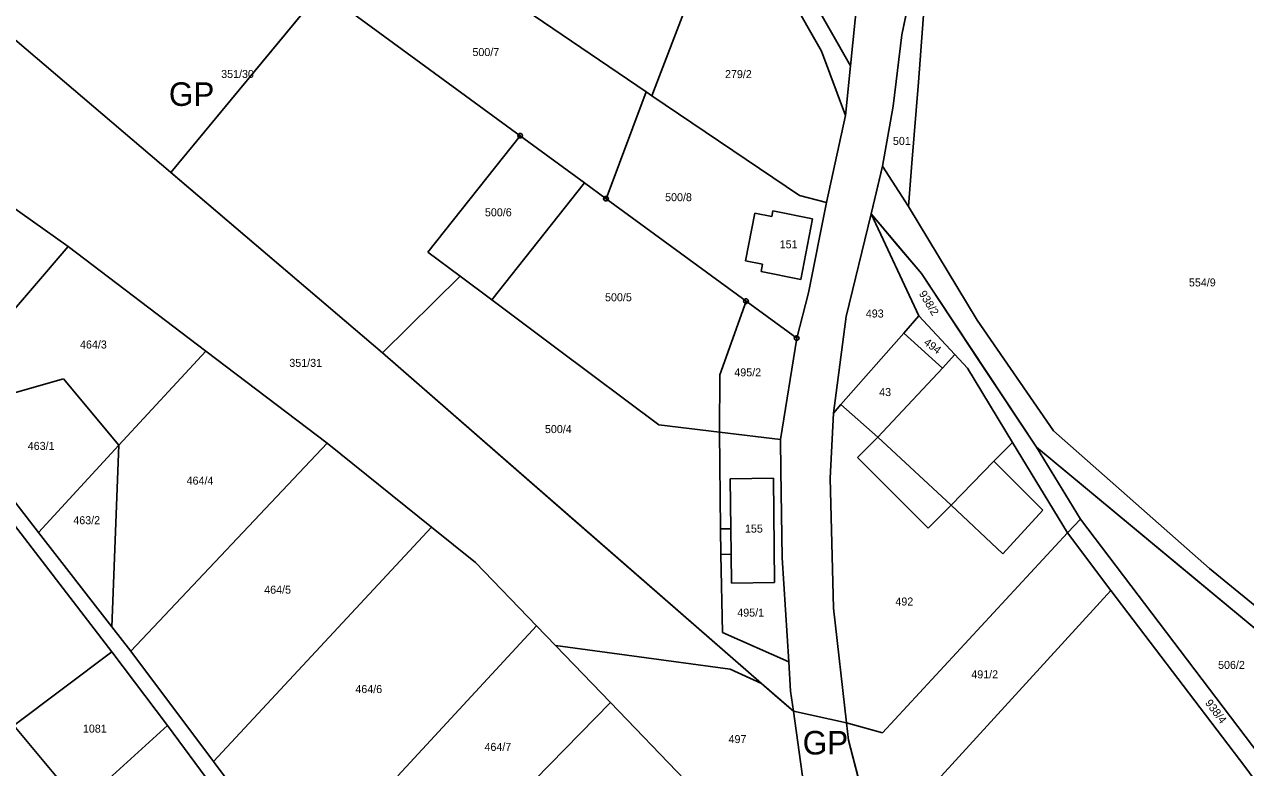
# Model space of a CAD drawing. Extents: x -593358 to -590116, y -1072518 to -1068420.
# Drawn here: x -591991 to -591731.6, y -1071381.6 to -1071223.8 of the extents above; entities that cross this region are included whole.
import ezdxf

# ---------------------------------------------------------------- set-up
doc = ezdxf.new("R2010")
doc.units = 0
for name, color, linetype in [('GP', 7, 'Continuous'), ('Parcela KN', 7, 'Continuous'), ('Parcela ZE', 7, 'Continuous'), ('Parcelní číslo', 7, 'Continuous'), ('Parcelní číslo_stavební', 7, 'Continuous'), ('stavby - vnitřní kresba', 7, 'Continuous'), ('Vnitřní obvod', 7, 'Continuous'), ('Vrstva 24', 7, 'Continuous')]:
    doc.layers.add(name, color=color, linetype=linetype)

msp = doc.modelspace()

# ---------------------------------------------------------------- linework, layer by layer
at = {"layer": 'GP'}
for p, q in [((-591927.89, -1071216.58), (-591959.895, -1071255.245)), ((-591827.65, -1071369.65), (-591816.36, -1071372.12))]:
    msp.add_line(p, q, dxfattribs=at)
at = {"layer": 'Parcela KN'}
for p, q in [((-591811.35, -1071191.44), (-591815.51, -1071232.63)), ((-591804.64, -1071226.05), (-591797.92, -1071193.88)), ((-591801.11, -1071236.11), (-591797.92, -1071193.88)), ((-591915.46, -1071199.67), (-591858.93, -1071238.14)), ((-591843.51, -1071202.01), (-591857.72, -1071238.98)), ((-591829.31, -1071216.03), (-591821.68, -1071229.47)), ((-591825.69, -1071214.74), (-591815.51, -1071232.63)), ((-591885.68, -1071247.47), (-591927.89, -1071216.58)), ((-591806.43, -1071241.17), (-591804.64, -1071226.05)), ((-591821.68, -1071229.47), (-591816.56, -1071243.14)), ((-591815.51, -1071232.63), (-591816.56, -1071243.14)), ((-591801.11, -1071236.11), (-591802.48, -1071253.26)), ((-591858.93, -1071238.14), (-591867.44, -1071260.82)), ((-591858.93, -1071238.14), (-591858.21, -1071238.63)), ((-591857.72, -1071238.98), (-591858.21, -1071238.63)), ((-591857.72, -1071238.98), (-591826.33, -1071260.13)), ((-591808.76, -1071253.92), (-591806.43, -1071241.17)), ((-591816.56, -1071243.14), (-591820.63, -1071261.64)), ((-591885.68, -1071247.47), (-591905.3, -1071272.14)), ((-591885.68, -1071247.47), (-591872, -1071257.48)), ((-591811.14, -1071264.07), (-591808.76, -1071253.92)), ((-591808.76, -1071253.92), (-591803.22, -1071262.48)), ((-591802.48, -1071253.26), (-591803.22, -1071262.48)), ((-591872, -1071257.48), (-591891.72, -1071282.28)), ((-591872, -1071257.48), (-591867.44, -1071260.82)), ((-591826.33, -1071260.13), (-591820.63, -1071261.64)), ((-591867.44, -1071260.82), (-591837.71, -1071282.58)), ((-591820.63, -1071261.64), (-591824.43, -1071280.83)), ((-591803.22, -1071262.48), (-591788.63, -1071286.6)), ((-591835.86, -1071263.9), (-591837.84, -1071274.01)), ((-591832.23, -1071264.61), (-591835.86, -1071263.9)), ((-591832, -1071263.43), (-591832.23, -1071264.61)), ((-591823.6, -1071265.11), (-591832, -1071263.43)), ((-591826.07, -1071277.95), (-591823.6, -1071265.11)), ((-591811.14, -1071264.07), (-591816.47, -1071285.84)), ((-591800.47, -1071276.72), (-591811.14, -1071264.07)), ((-591811.14, -1071264.07), (-591801, -1071285.7)), ((-591905.3, -1071272.14), (-591898.39, -1071277.29)), ((-591837.84, -1071274.01), (-591834.2, -1071274.72)), ((-591834.2, -1071274.72), (-591834.51, -1071276.29)), ((-591898.39, -1071277.29), (-591914.91, -1071293.58)), ((-591898.39, -1071277.29), (-591891.72, -1071282.28)), ((-591834.51, -1071276.29), (-591826.07, -1071277.95)), ((-591776, -1071313.59), (-591800.47, -1071276.72)), ((-591824.43, -1071280.83), (-591826.95, -1071290.45)), ((-591891.72, -1071282.28), (-591877.8, -1071292.68)), ((-591843.28, -1071298.24), (-591837.71, -1071282.58)), ((-591837.71, -1071282.58), (-591826.95, -1071290.45)), ((-591816.47, -1071285.84), (-591819.12, -1071306.37)), ((-591804.22, -1071289.36), (-591801, -1071285.7)), ((-591801, -1071285.7), (-591793.35, -1071293.87)), ((-591788.63, -1071286.6), (-591772.44, -1071310.09)), ((-591830.36, -1071311.96), (-591826.95, -1071290.45)), ((-591804.22, -1071289.36), (-591817.6, -1071304.55)), ((-591795.95, -1071296.77), (-591804.22, -1071289.36)), ((-591914.91, -1071293.58), (-591834.43, -1071363.74)), ((-591877.8, -1071292.68), (-591856.2, -1071308.84)), ((-591793.35, -1071293.87), (-591795.95, -1071296.77)), ((-591793.35, -1071293.87), (-591790.71, -1071296.8)), ((-591790.71, -1071296.8), (-591781.14, -1071312.56)), ((-591843.34, -1071310.39), (-591843.28, -1071298.24)), ((-591817.6, -1071304.55), (-591819.12, -1071306.37)), ((-591817.6, -1071304.55), (-591809.71, -1071311.44)), ((-592007.75, -1071306.19), (-591987.97, -1071331.66)), ((-591819.12, -1071306.37), (-591819.85, -1071320.19)), ((-591972.38, -1071357.06), (-592008.72, -1071309.86)), ((-591856.2, -1071308.84), (-591843.34, -1071310.39)), ((-591843.12, -1071330.95), (-591843.34, -1071310.39)), ((-591843.34, -1071310.39), (-591830.36, -1071311.96)), ((-591830.34, -1071318.56), (-591830.36, -1071311.96)), ((-591809.71, -1071311.44), (-591814.05, -1071315.78)), ((-591772.44, -1071310.09), (-591739.25, -1071339.36)), ((-591785.05, -1071316.57), (-591781.14, -1071312.56)), ((-591781.14, -1071312.56), (-591769.45, -1071331.8)), ((-591766.67, -1071328.84), (-591776, -1071313.59)), ((-591709.25, -1071369), (-591776, -1071313.59)), ((-591814.05, -1071315.78), (-591799.02, -1071330.81)), ((-591774.7, -1071326.96), (-591785.05, -1071316.57)), ((-591831.85, -1071320.19), (-591841.06, -1071320.31)), ((-591831.63, -1071342.33), (-591831.85, -1071320.19)), ((-591830.06, -1071337.08), (-591830.34, -1071318.56)), ((-591819.85, -1071320.19), (-591819.11, -1071347.73)), ((-591841.06, -1071320.31), (-591840.91, -1071330.92)), ((-591799.02, -1071330.81), (-591794.12, -1071325.86)), ((-591794.12, -1071325.86), (-591783.17, -1071336.24)), ((-591783.17, -1071336.24), (-591774.7, -1071326.96)), ((-591766.67, -1071328.84), (-591769.45, -1071331.8)), ((-591766.67, -1071328.84), (-591723.27, -1071386.12)), ((-591987.97, -1071331.66), (-591972.41, -1071351.69)), ((-591840.91, -1071330.92), (-591843.12, -1071330.95)), ((-591843.12, -1071330.95), (-591843.04, -1071336.35)), ((-591769.45, -1071331.8), (-591808.73, -1071374.21)), ((-591769.45, -1071331.8), (-591760.24, -1071344)), ((-591843.04, -1071336.35), (-591840.84, -1071336.33)), ((-591843.04, -1071336.35), (-591842.69, -1071352.91)), ((-591840.84, -1071336.33), (-591840.76, -1071342.48)), ((-591828.65, -1071359.12), (-591830.06, -1071337.08)), ((-591739.25, -1071339.36), (-591700.13, -1071371.4)), ((-591840.76, -1071342.48), (-591831.63, -1071342.33)), ((-591760.24, -1071344), (-591809.83, -1071398.21)), ((-591760.24, -1071344), (-591731.77, -1071381.41)), ((-591819.11, -1071347.73), (-591816.36, -1071372.12)), ((-591972.41, -1071351.69), (-591968.37, -1071356.89)), ((-591842.69, -1071352.91), (-591828.65, -1071359.12)), ((-591960.54, -1071372.64), (-591972.38, -1071357.06)), ((-591968.37, -1071356.89), (-591950.79, -1071380.34)), ((-591828.25, -1071365.39), (-591828.65, -1071359.12)), ((-591834.43, -1071363.74), (-591827.65, -1071369.65)), ((-591827.65, -1071369.65), (-591828.25, -1071365.39)), ((-591825.5, -1071385.01), (-591827.65, -1071369.65)), ((-591808.73, -1071374.21), (-591816.36, -1071372.12)), ((-591816.36, -1071372.12), (-591815.94, -1071375.81)), ((-591951.17, -1071385.39), (-591960.54, -1071372.64)), ((-591815.94, -1071375.81), (-591810.96, -1071394.77)), ((-591950.79, -1071380.34), (-591932.36, -1071404.92)), ((-591731.77, -1071381.41), (-591711.1, -1071409.24))]:
    msp.add_line(p, q, dxfattribs=at)
at = {"layer": 'Parcela ZE'}
for p, q in [((-592004.88, -1071216.91), (-591914.91, -1071293.58)), ((-592025.24, -1071240.02), (-591981.68, -1071271)), ((-591981.68, -1071271), (-592009.73, -1071303.65)), ((-591981.68, -1071271), (-591952.46, -1071293.17)), ((-591952.46, -1071293.17), (-591970.89, -1071313.14)), ((-591952.46, -1071293.17), (-591926.69, -1071312.72)), ((-592007.75, -1071306.19), (-591982.67, -1071299.08)), ((-591982.67, -1071299.08), (-591970.89, -1071313.14)), ((-591970.89, -1071313.14), (-591987.97, -1071331.66)), ((-591970.89, -1071313.14), (-591972.41, -1071351.69)), ((-591926.69, -1071312.72), (-591968.37, -1071356.89)), ((-591926.69, -1071312.72), (-591904.54, -1071330.53)), ((-591904.54, -1071330.53), (-591950.79, -1071380.34)), ((-591904.54, -1071330.53), (-591895.19, -1071338.04)), ((-591895.19, -1071338.04), (-591882.24, -1071351.48)), ((-591911.66, -1071383.38), (-591882.24, -1071351.48)), ((-591882.24, -1071351.48), (-591878.16, -1071355.71)), ((-591878.16, -1071355.71), (-591866.52, -1071367.79)), ((-591878.16, -1071355.71), (-591841.11, -1071360.73)), ((-591993.2, -1071372.7), (-591972.38, -1071357.06)), ((-591841.11, -1071360.73), (-591834.43, -1071363.74)), ((-591897.49, -1071399.39), (-591866.52, -1071367.79)), ((-591866.52, -1071367.79), (-591850.68, -1071384.24)), ((-591993.2, -1071372.7), (-591979.13, -1071389.5)), ((-591979.13, -1071389.5), (-591960.54, -1071372.64))]:
    msp.add_line(p, q, dxfattribs=at)
at = {"layer": 'stavby - vnitřní kresba'}
for p, q in [((-591809.71, -1071311.44), (-591795.95, -1071296.77)), ((-591794.12, -1071325.86), (-591809.71, -1071311.44)), ((-591794.12, -1071325.86), (-591785.05, -1071316.57)), ((-591840.91, -1071330.92), (-591840.84, -1071336.33))]:
    msp.add_line(p, q, dxfattribs=at)
at = {"layer": 'Vnitřní obvod'}
for p, q in [((-591805.805, -1071270.395), (-591811.14, -1071264.07)), ((-591800.47, -1071276.72), (-591805.805, -1071270.395)), ((-591788.235, -1071295.155), (-591800.47, -1071276.72)), ((-591776, -1071313.59), (-591788.235, -1071295.155)), ((-591742.625, -1071341.295), (-591776, -1071313.59)), ((-591709.25, -1071369), (-591742.625, -1071341.295))]:
    msp.add_line(p, q, dxfattribs=at)
for points in [[(-591811.14, -1071264.07), (-591809.95, -1071258.995), (-591808.76, -1071253.92), (-591807.595, -1071247.545), (-591806.43, -1071241.17), (-591805.535, -1071233.61), (-591804.64, -1071226.05), (-591801.28, -1071209.965), (-591797.92, -1071193.88), (-591795.54, -1071182.89), (-591793.16, -1071171.9)], [(-591915.46, -1071199.67), (-591921.675, -1071208.125), (-591927.89, -1071216.58), (-591959.895, -1071255.245), (-591914.91, -1071293.58)], [(-591914.91, -1071293.58), (-591874.67, -1071328.66), (-591834.43, -1071363.74), (-591831.04, -1071366.695), (-591827.65, -1071369.65)], [(-591827.65, -1071369.65), (-591816.36, -1071372.12), (-591816.15, -1071373.965), (-591815.94, -1071375.81), (-591813.45, -1071385.29), (-591810.96, -1071394.77), (-591810.395, -1071396.49), (-591809.83, -1071398.21), (-591805.31, -1071412.015), (-591800.79, -1071425.82), (-591800, -1071428.24), (-591799.21, -1071430.66), (-591793.84, -1071447.055), (-591788.47, -1071463.45), (-591781.43, -1071483.605), (-591774.39, -1071503.76), (-591773.375, -1071506.675), (-591772.36, -1071509.59), (-591772.05, -1071512.275), (-591771.74, -1071514.96), (-591770.11, -1071529.055), (-591768.48, -1071543.15), (-591769.415, -1071544.19), (-591770.35, -1071545.23)]]:
    msp.add_lwpolyline(points, dxfattribs=at)
at = {"layer": 'Vrstva 24'}
for p, q in [((-591885.8, -1071247.47), (-591885.56, -1071247.47)), ((-591867.56, -1071260.82), (-591867.32, -1071260.82)), ((-591837.83, -1071282.58), (-591837.59, -1071282.58)), ((-591827.07, -1071290.45), (-591826.83, -1071290.45))]:
    msp.add_line(p, q, dxfattribs=at)
for points in [[(-591885.53, -1071246.99), (-591885.28, -1071247.17), (-591885.18, -1071247.46), (-591885.28, -1071247.75), (-591885.53, -1071247.93), (-591885.84, -1071247.93), (-591886.09, -1071247.75), (-591886.19, -1071247.46), (-591886.09, -1071247.17), (-591885.84, -1071246.99)], [(-591867.29, -1071260.34), (-591867.04, -1071260.52), (-591866.94, -1071260.81), (-591867.04, -1071261.1), (-591867.29, -1071261.28), (-591867.6, -1071261.28), (-591867.85, -1071261.1), (-591867.95, -1071260.81), (-591867.85, -1071260.52), (-591867.6, -1071260.34)], [(-591837.56, -1071282.1), (-591837.31, -1071282.28), (-591837.21, -1071282.57), (-591837.31, -1071282.86), (-591837.56, -1071283.04), (-591837.87, -1071283.04), (-591838.12, -1071282.86), (-591838.22, -1071282.57), (-591838.12, -1071282.28), (-591837.87, -1071282.1)], [(-591826.8, -1071289.97), (-591826.55, -1071290.15), (-591826.45, -1071290.44), (-591826.55, -1071290.73), (-591826.8, -1071290.91), (-591827.11, -1071290.91), (-591827.36, -1071290.73), (-591827.46, -1071290.44), (-591827.36, -1071290.15), (-591827.11, -1071289.97)]]:
    msp.add_lwpolyline(points, close=True, dxfattribs=at)

# ---------------------------------------------------------------- texts
at = {"layer": 'GP'}
for p in [(-591960.281, -1071241.119), (-591825.674, -1071378.829)]:
    msp.add_text('GP', height=5, dxfattribs=at).set_placement(p)
at = {"layer": 'Parcelní číslo'}
for s, p in [('500/7', (-591895.813, -1071230.54)), ('351/30', (-591949.172, -1071235.19)), ('279/2', (-591842.17, -1071235.22)), ('501', (-591806.51, -1071249.41)), ('500/8', (-591854.894, -1071261.35)), ('500/6', (-591893.154, -1071264.56)), ('554/9', (-591743.647, -1071279.45)), ('500/5', (-591867.65, -1071282.6)), ('493', (-591812.271, -1071286.05)), ('464/3', (-591979.15, -1071292.63)), ('351/31', (-591934.697, -1071296.53)), ('495/2', (-591840.194, -1071298.54)), ('500/4', (-591880.414, -1071310.59)), ('463/1', (-591990.252, -1071314.16)), ('464/4', (-591956.513, -1071321.53)), ('463/2', (-591980.574, -1071329.94)), ('464/5', (-591940.03, -1071344.68)), ('492', (-591805.988, -1071347.2)), ('495/1', (-591839.572, -1071349.55)), ('506/2', (-591737.46, -1071360.66)), ('491/2', (-591789.869, -1071362.66)), ('464/6', (-591920.673, -1071365.79)), ('1081', (-591978.531, -1071374.18)), ('497', (-591841.424, -1071376.41)), ('464/7', (-591893.253, -1071378.07))]:
    msp.add_text(s, height=1.7, dxfattribs=at).set_placement(p)
for s, rotation, p in [('938/2', 301.3758, (-591801.065, -1071280.969)), ('494', 323.54927, (-591800.112, -1071291.659)), ('938/4', 306.99079, (-591740.304, -1071367.907))]:
    msp.add_text(s, height=1.7, rotation=rotation, dxfattribs=at).set_placement(p)
at = {"layer": 'Parcelní číslo_stavební'}
for s, p in [('151', (-591830.555, -1071271.36)), ('43', (-591809.432, -1071302.73)), ('155', (-591837.93, -1071331.72))]:
    msp.add_text(s, height=1.7, dxfattribs=at).set_placement(p)

doc.saveas('drawing.dxf')
